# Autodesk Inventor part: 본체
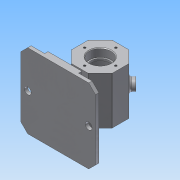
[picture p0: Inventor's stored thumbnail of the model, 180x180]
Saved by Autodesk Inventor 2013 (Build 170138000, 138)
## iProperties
Created: 2018-06
Part Number: 본체
Material: 알루미늄 6061
Document SubType Name: Modeling
Designer: Administrator
Density: 2.71 g/cm^3
Mass: 554.043 g
Surface Area: 601.93 cm^2
Volume: 204.444 cm^3
Author: Administrator
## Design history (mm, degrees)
sketch "스케치1"
  geometry: L1 (-55, -62)-(55, -62); L2 (55, -62)-(55, -57); L3 (55, -57)-(25, -57); L4 (25, -57)-(25, -52); L5 (25, -52)-(-25, -52); L6 (-25, -52)-(-25, -57); L7 (-25, -57)-(-55, -57); L8 (-55, -57)-(-55, -62); L9 (0, 0)-(12.426, 30); L10 (0, 0)-(-12.426, 30); L11 (0, 0)-(0, 43.972); L12 (0, 0)-(-21.128, 0); L13 (12.426, 30)-(-12.426, 30); C1 r 30 at (0, 0); 1 further point
  constraints: 26 end point, 7 parallel, 2 perpendicular, 1 centre point, 1 coincident, 1 horizontal
  dimensions: "d0" = 60 diameter of C1; "d1" = 22.5 deg angle of L9 L11; "d3" = 22.5 deg angle of L11 L10; "d6" = 30 distance between parallel lines of L13 L12; "d7" = 92 distance from line of L1.start L13; "d8" = 110 distance of L1.start L1.end; "d9" = 55 horizontal distance of point (0, 0) L1.start; "d10" = 10 vertical distance of L4.end L1.end; "d11" = 5 distance of L3.end L4.end; "d12" = 5 distance of L5.end L6.end; "d13" = 30 distance between parallel lines of L6 L8; "d14" = 30 distance between parallel lines of L2 L4
extrude "돌출1" new body sketch "스케치1" stored distance "d15" = 110; taper "d16" = 0 deg
extrude "돌출2" join sketch "스케치1" stored distance "d17" = 70; taper "d18" = 0 deg
sketch "스케치2"
  geometry: L1 (0, 110)-(50, 110) reference; L2 (20, 74)-(20, 36); L3 (30, 36)-(30, 74); L4 (25, 55)-(6.101, 55); A1 r 5 centre (25, 36) between (20, 36) and (30, 36); A2 r 5 centre (25, 74) between (30, 74) and (20, 74)
  constraints: 6 end point, 4 point on circle, 4 tangent, 2 centre point, 2 perpendicular, 1 parallel, 1 vertical alignment
  dimensions: "d24" = 10 distance between parallel lines of L3 L2; "d26" = 38 distance of A1.centre A2.centre; "d27" = 24 dimension on A2 L4
extrude "돌출3" join sketch "스케치2" stored distance "d28" = 70; taper "d29" = 0 deg
sketch "스케치3"
  geometry: L1 (30, 110)-(30, 0) reference; C1 r 5 at (20, 55); 1 further point
  constraints: 1 centre point, 1 horizontal alignment
  dimensions: "d30" = 10 diameter of C1; "d31" = 10 distance from line of C1.centre L1
extrude "돌출4" cut sketch "스케치3" distance "d32" = 70; taper "d33" = 0 deg
sketch "스케치5"
  geometry: 1 further point
hole "구멍1" sketch "스케치5" at (0, 0) diameter "d34" = 28; stored, may be unused: countersink angle "d38" = 90 deg, drill point angle "d40" = 0 deg; dims "d35" = 6, "d36" = 32, "d37" = 12, "d39" = 15
sketch "스케치6"
  geometry: 1 further point
hole "구멍2" sketch "스케치6" at (0, 0) diameter "d41" = 28; stored, may be unused: countersink angle "d45" = 90 deg, drill point angle "d47" = 0 deg; dims "d42" = 6, "d43" = 32, "d44" = 12, "d46" = 15
hole "구멍3" diameter "d50" = 50; stored, may be unused: countersink angle "d54" = 90 deg, drill point angle "d56" = 0 deg; dims "d48" = 10, "d49" = 10, "d51" = 6, "d52" = 32, "d53" = 12, "d55" = 40
sketch "스케치7"
  geometry: C1 r 16 at (0, 0) reference; 1 further point
  constraints: 1 vertical alignment
  dimensions: "d57" = 23 distance of point (0, 23) C1.centre
hole "구멍4" sketch "스케치7" at (0, 23) diameter "d58" = 3.242; stored, may be unused: countersink angle "d62" = 90 deg, drill point angle "d64" = 118 deg; dims "d59" = 8, "d60" = 32, "d61" = 12, "d63" = 10
sketch "스케치8"
  geometry: L1 (24.853, 0)-(0, 0) reference; L2 (-17.574, 70)-(-17.574, 0) reference; 2 further points
  constraints: 1 other
  dimensions: "d68" = 30 distance from line of L2 point (12.426, 35); "d69" = 35 distance from line of L1 point (12.426, 35)
feature "엠보싱1" sketch "스케치8" dims "d70" = 0.5, "d71" = 0
node "작업 평면1"
sketch "스케치9"
  geometry: L1 (50, -62)-(50, -57) reference; L2 (50, -57)-(55, -57) reference; L3 (55, -57)-(55, -62) reference; L4 (55, -62)-(50, -62) reference; L5 (5, -30)-(5, -52) reference; L6 (5, -52)-(25, -52) reference; L7 (25, -52)-(25, -57) reference; L8 (25, -57)-(40, -57) reference; L9 (40, -57)-(40, -62) reference; L10 (40, -62)-(-40, -62) reference; L11 (-40, -62)-(-40, -57) reference; L12 (-40, -57)-(-25, -57) reference; L13 (-25, -57)-(-25, -52) reference; L14 (-25, -52)-(-5, -52) reference; L15 (-5, -52)-(-5, -30) reference; L16 (-5, -30)-(-12.426, -30) reference; L17 (-12.426, -30)-(-30, -12.426) reference; L18 (-30, -12.426)-(-30, 12.426) reference; L19 (-30, 12.426)-(-12.426, 30) reference; L20 (-12.426, 30)-(-2.862, 30) reference; L21 (-2.862, 30)-(-2.862, 30.5) reference; L22 (-2.862, 30.5)-(-2.365, 30.5) reference; L23 (-2.365, 30.5)-(-2.365, 30) reference; L24 (-2.365, 30)-(12.426, 30) reference; L25 (12.426, 30)-(30, 12.426) reference; L26 (30, 12.426)-(30, -12.426) reference; L27 (30, -12.426)-(12.426, -30) reference; L28 (12.426, -30)-(5, -30) reference; L29 (-55, -62)-(-55, -57) reference; L30 (-55, -57)-(-50, -57) reference; L31 (-50, -57)-(-50, -62) reference; L32 (-50, -62)-(-55, -62) reference; L33 (0, 0)-(26.163, 26.163); C1 r 25 at (0, 0) reference; 1 further point
  constraints: 2 end point, 1 parallel
  dimensions: "d73" = 37 distance of L33.start L33.end
  node "절단 모서리 투영1"
node "작업 평면2"
sketch "스케치10"
  geometry: C1 r 8 at (0, 0); 1 further point
  constraints: 1 centre point, 1 coincident
  dimensions: "d74" = 16 diameter of C1
extrude "돌출5" join sketch "스케치10" stored distance "d75" = 70; taper "d76" = 0 deg
hole "구멍5" diameter "d79" = 8; stored, may be unused: countersink angle "d83" = 90 deg, drill point angle "d85" = 0 deg; dims "d77" = 10, "d78" = 10, "d80" = 8, "d81" = 32, "d82" = 12, "d84" = 10
chamfer "모따기1" distance "d86" = 10; stored, may be unused: second distance "d87" = 2, angle "d88" = 45 deg
chamfer "모따기2" distance "d89" = 1; stored, may be unused: second distance "d90" = 2, angle "d91" = 45 deg
fillet "모깎기1" dims "d92" = 1, "d93" = 2, "d94" = 3, "d95" = 0.3
node "솔리드1"
pattern_circular "원형 패턴1" dims angle "d20" = 360 deg
mirror "대칭1"
pattern_circular "원형 패턴2" dims angle "d66" = 360 deg
mirror "대칭2"
other parameters: "d72" = 0
